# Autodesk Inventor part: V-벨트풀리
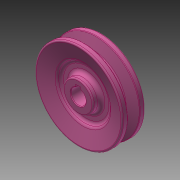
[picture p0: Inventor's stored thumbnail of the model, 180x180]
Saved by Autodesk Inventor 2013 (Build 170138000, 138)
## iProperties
Created: 2016-08
Part Number: V-벨트풀리
Material: 알루미늄 6061
Document SubType Name: Modeling
Designer: mduedu
Density: 2.71 g/cm^3
Author: mduedu
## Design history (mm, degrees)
sketch "스케치1"
  geometry: L1 (0, 10)-(0, -10); L2 (0, 10)-(40, 10); L3 (40, 10)-(40, 5.976); L4 (40, 5.976)-(27.5, 2.154); L5 (27.5, 2.154)-(27.5, 0); L6 (0, 0)-(27.5, 0); L7 (0, -10)-(40, -10); L8 (40, -10)-(40, -5.976); L9 (40, -5.976)-(27.5, -2.154); L10 (27.5, -2.154)-(27.5, 0); L11 (35.5, 10)-(35.5, -10); 3 further points
  constraints: 22 end point, 6 point on line, 4 perpendicular, 3 symmetric about line, 1 coincident, 1 horizontal alignment, 1 midpoint, 1 parallel, 1 vertical
  dimensions: "d0" = 20 distance of L1.start L1.end; "d2" = 80 diameter of L8 L1; "d4" = 8 distance between parallel lines of L10 L11; "d5" = 4.5 distance between parallel lines of L11 L8; "d6" = 9.2 distance of point (35.5, -4.6) point (35.5, 4.6); "d7" = 34 deg angle of L9 L4
revolve "회전1" sketch "스케치1" stored, may be unused: angle "d8" = 90 deg
sketch "스케치2"
  geometry: L1 (-2, 0)-(2, 0); L2 (2, 0)-(2, 7.8); L3 (2, 7.8)-(-2, 7.8); L4 (-2, 7.8)-(-2, 0); C1 r 6 at (0, 0); 2 further points
  constraints: 8 end point, 2 coincident, 2 parallel, 1 centre point, 1 horizontal, 1 midpoint, 1 perpendicular
  dimensions: "d9" = 12 diameter of C1; "d11" = 4 distance of L2.end L3.end; "d12" = 7.8 distance of L1.end L2.end
extrude "돌출1" cut sketch "스케치2" stored distance "d13" = 10; taper "d14" = 0 deg
sketch "스케치3"
  geometry: L1 (40, 5.976)-(27.5, 2.154) reference; L2 (27.5, 2.154)-(27.5, -2.154) reference; L3 (0, 0)-(27.5, 0); L4 (40, 10)-(40, 5.976) reference; L5 (-40, 10)-(40, 10) reference; L6 (21.5, 10)-(21.5, 3); L7 (21.5, 3)-(12, 3); L8 (12, 3)-(12, 10); L9 (0, 10)-(0, -10); L10 (5.657, -10)-(-6, -10) reference; L11 (12, 10)-(21.5, 10)
  constraints: 12 end point, 3 midpoint, 2 perpendicular, 2 point on line, 1 collinear, 1 horizontal, 1 parallel
  dimensions: "d15" = 3 distance between parallel lines of L3 L7; "d17" = 43 diameter of L6 L9; "d18" = 24 diameter of L8 L9
revolve "회전2" sketch "스케치3" stored, may be unused: angle "d19" = 90 deg
fillet "모깎기1" dims "d20" = 1, "d21" = 0.5, "d22" = 2
fillet "모깎기2" dims "d23" = 3
fillet "모깎기3" dims "d24" = 3
fillet "모깎기4" dims "d25" = 3
chamfer "모따기1" distance "d26" = 0.5; stored, may be unused: second distance "d27" = 2, angle "d28" = 45 deg
fillet "모깎기5" dims "d29" = 1
node "솔리드1"
mirror "대칭1"
